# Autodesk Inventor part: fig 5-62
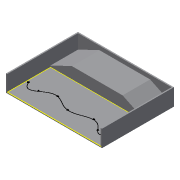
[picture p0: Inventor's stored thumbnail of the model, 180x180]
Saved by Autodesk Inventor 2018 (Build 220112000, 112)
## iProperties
Created: 2004-05
Part Number: fig 5-62
Document SubType Name: Modeling
Designer: CADCIM Technologies
Manufacturer: Standard
Standards Organization: Custom
Density: 1 g/cm^3
Material: Generic
Appearance: Default
Author: CADCIM Technologies
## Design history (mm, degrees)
sketch "Sketch1"
  geometry: L1 (-40, -30)-(40, -30); L2 (40, -30)-(40, 30); L3 (40, 30)-(-40, 30); L4 (-40, 30)-(-40, -30); 1 further point
  constraints: 8 end point, 2 parallel, 1 horizontal, 1 perpendicular, 1 other
  dimensions: "d0" = 80 distance of L1.start L1.end; "d1" = 60 distance of L3.end L1.start; "d2" = 30 distance from line of point (0, 0) L1; "d3" = 40 distance from line of point (0, 0) L4
extrude "Extrusion1" new body sketch "Sketch1" distance "d4" = 14; taper "d5" = 0 deg
shell "Shell1" dims "d6" = 1
workplane "Work Plane1"
sketch "Sketch2"
  geometry: L1 (78, -13)-(78, -11.813); L2 (0, -11.813)-(0, -13); L3 (0, -13)-(78, -13); L4 (0, -11.813)-(17.826, -3.295); L5 (17.826, -3.295)-(60.174, -3.295); L6 (60.174, -3.295)-(78, -11.813); L7 (79, -13.795)-(78, -13.795); L8 (78, 0)-(78, -13) reference; L9 (0, -13)-(0, 0) reference; L10 (78, -13)-(0, -13) reference
  constraints: 14 end point, 3 collinear, 2 equal length, 2 vertical, 1 horizontal alignment, 1 parallel, 1 point on line
extrude "Extrusion2" join sketch "Sketch2" stored distance "d8" = 14; taper "d9" = 0 deg
workplane "Work Plane2"
sketch "Sketch4"
  geometry: L1 (78, 36)-(0, 36) reference; L2 (0, 36)-(0, 0) reference; L3 (78, 0)-(0, 0) reference; L4 (78, 0)-(78, 36) reference; 7 further points
  constraints: 7 other
body "Solid1"
other parameters: "d7" = 23, "d18" = 4
